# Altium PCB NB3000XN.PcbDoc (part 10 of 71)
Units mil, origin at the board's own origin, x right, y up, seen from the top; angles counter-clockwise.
Board outline 9527.56 x 6929.77 mil, 6 copper layers (Top Layer, GND+SHIELD, MidLayer1, MidLayer2, P2 - 3V3+5V0, Bottom Layer), stack 62.375 mil thick; 832 components, 1027 nets, 4655 pads, 4981 vias.
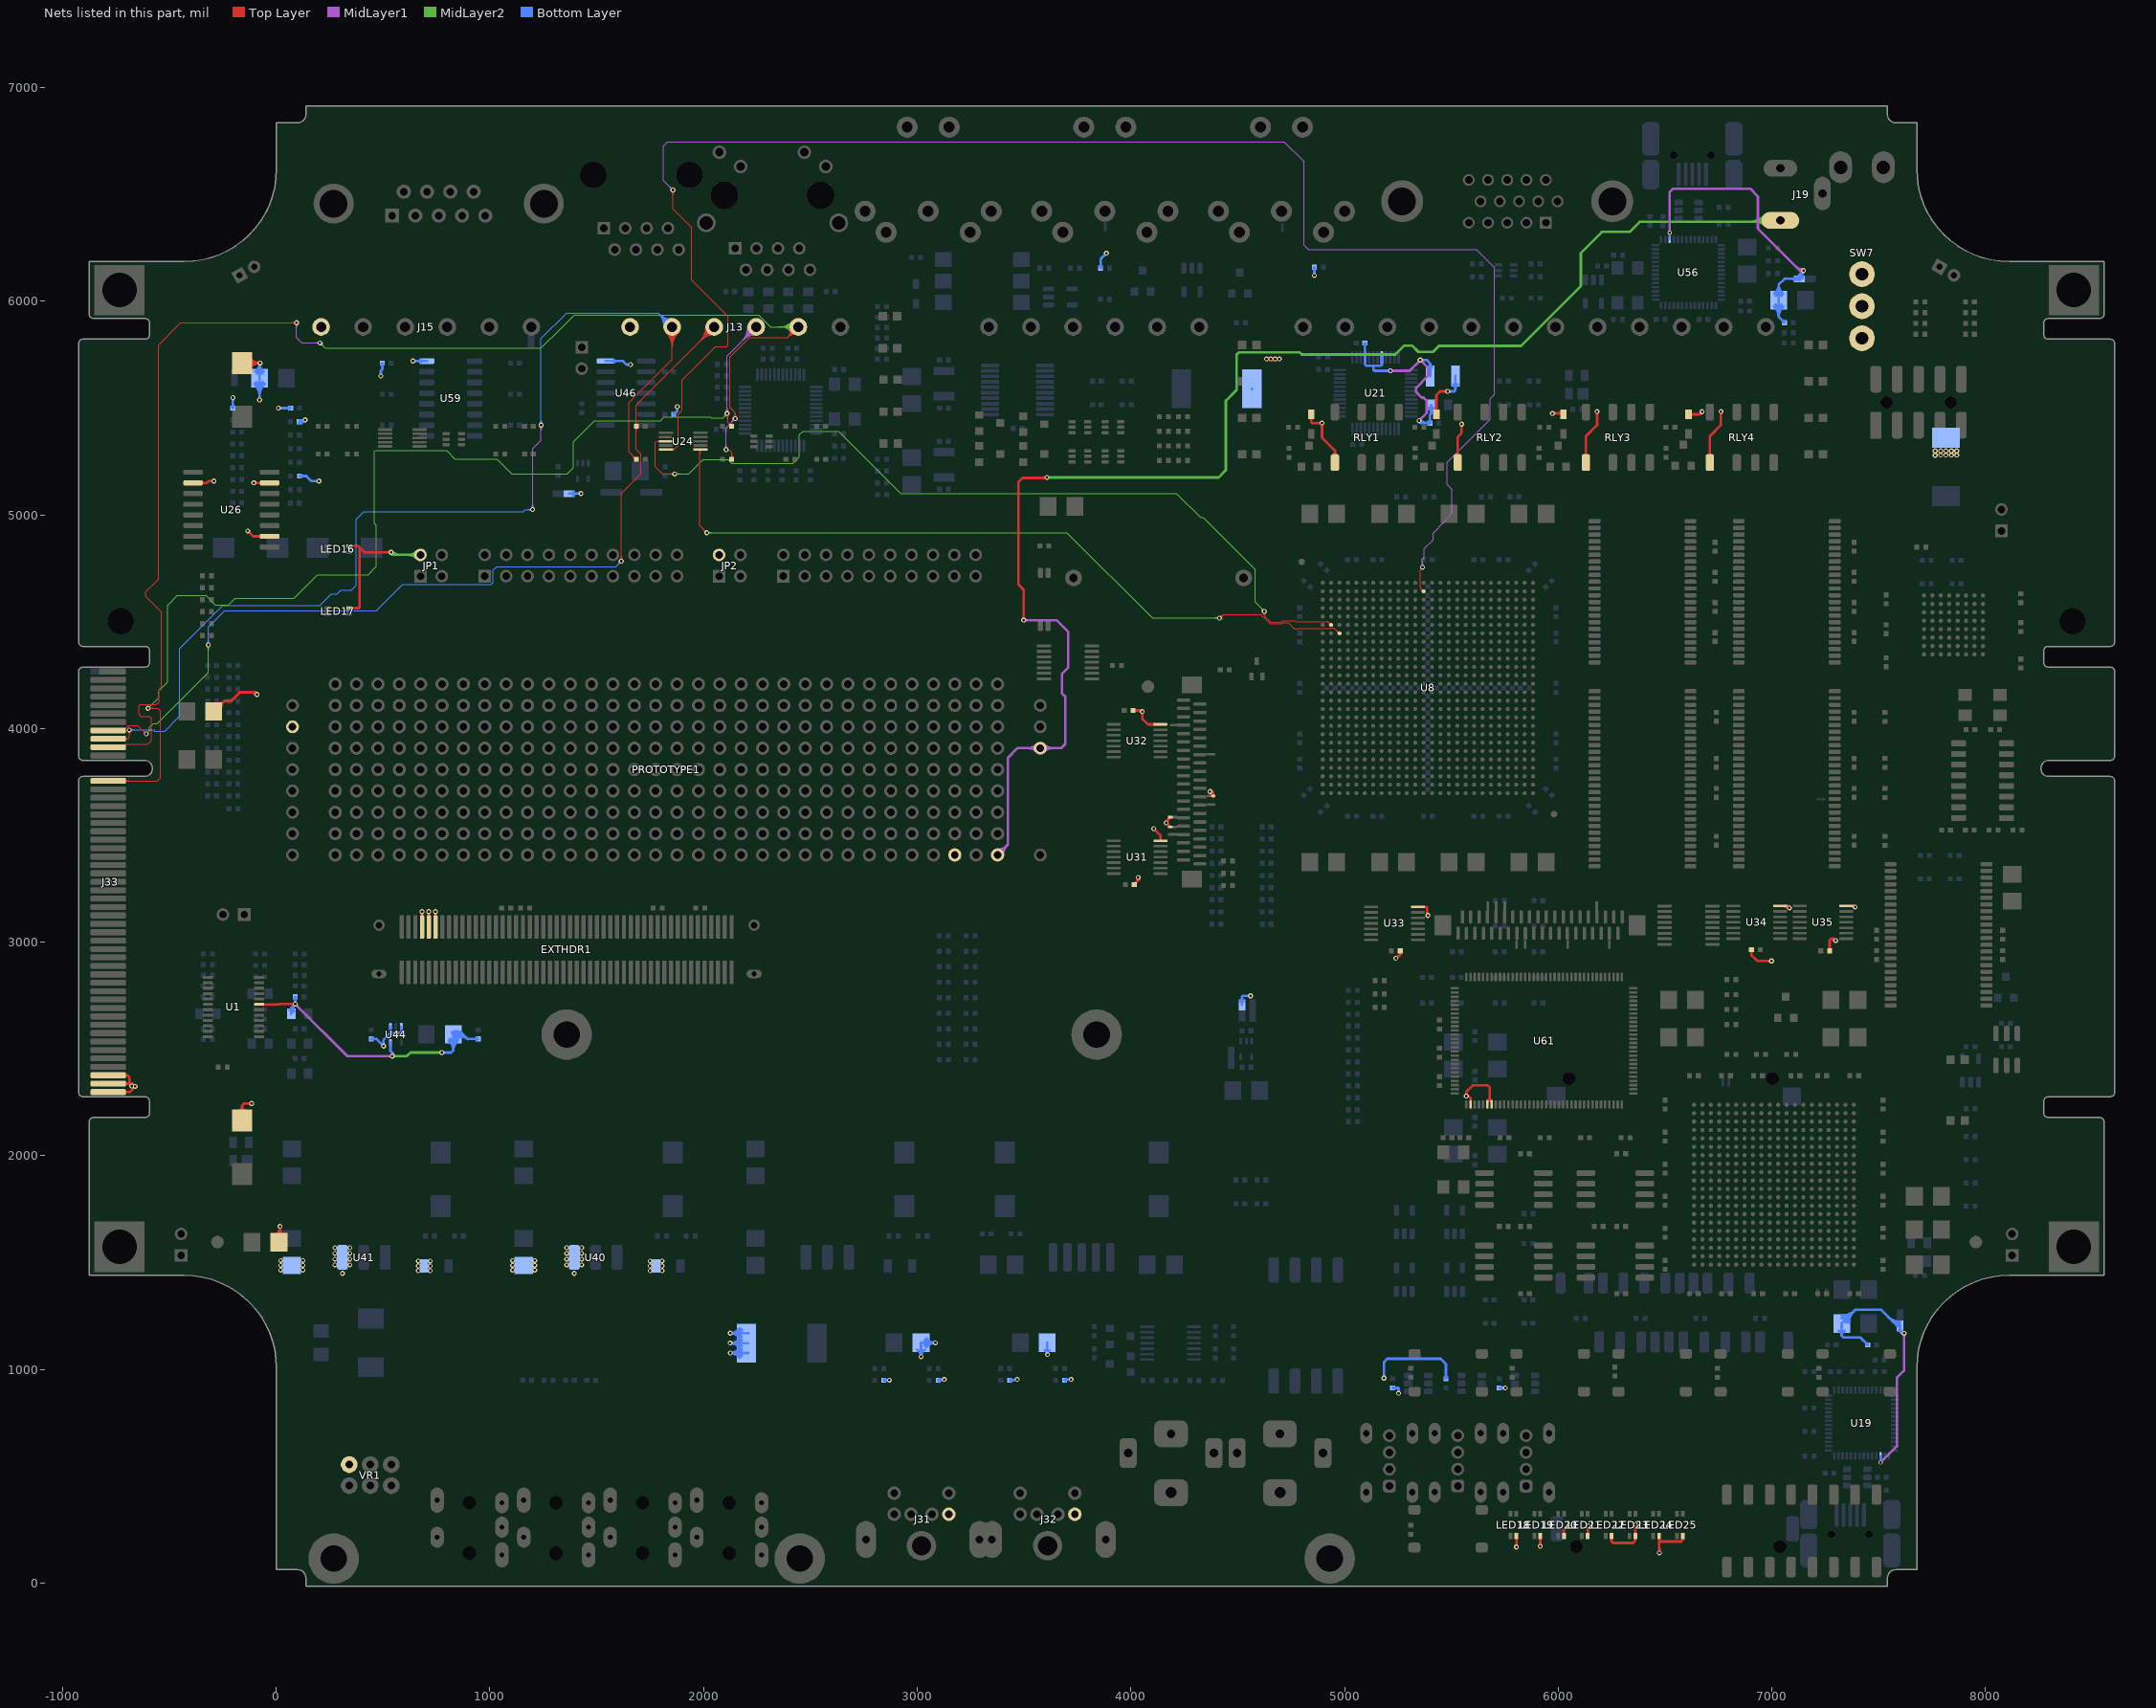
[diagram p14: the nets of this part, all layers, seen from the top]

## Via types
v1: diameter 23, hole 11.81, Top Layer to Bottom Layer, 3672 vias
v2: diameter 26, hole 11.81, Top Layer to Bottom Layer, 461 vias
v3: diameter 19, hole 11.81, Top Layer to Bottom Layer, tented both sides, 396 vias
v4: diameter 23.62, hole 11.81, Top Layer to Bottom Layer, 288 vias
v5: diameter 20, hole 11.81, Top Layer to Bottom Layer, 91 vias
v6: diameter 23, hole 11.81, Top Layer to Bottom Layer, tented both sides, 50 vias
v7: diameter 31, hole 11.81, Top Layer to Bottom Layer, 15 vias
v8: diameter 27.56, hole 11.81, Top Layer to Bottom Layer, tented both sides, 4 vias
v9: diameter 29, hole 11.81, Top Layer to Bottom Layer, 3 vias
v10: diameter 21, hole 11.81, Top Layer to Bottom Layer, 1 vias

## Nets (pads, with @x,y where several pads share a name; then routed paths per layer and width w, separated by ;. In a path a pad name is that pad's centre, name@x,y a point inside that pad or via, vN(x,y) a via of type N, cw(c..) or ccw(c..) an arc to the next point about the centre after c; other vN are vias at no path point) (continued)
5V0: C1.1 C2.1 C3.1 C4.1 C61.1 C62.1 C111.1 C112.2 C113.2 C114.2 C121.2 C122.2 C123.2 C124.2 C125.2 C130.1 C131.1 C134.1 C135.1 C145.2 C149.1 C152.2 D3.2 D4.2 D5.2 D6.2 EXTHDR1.89 EXTHDR1.91 EXTHDR1.93 F1.1 F2.2 J13.1 J15.1 J31.4 J32.4 J33.A47 J33.A48 J33.A49 JP1.2 JP2.2 L3.1 LED16.2 LED17.2 LED18.2 LED19.2 LED20.2 LED21.2 LED22.2 LED23.2 LED24.2 LED25.2 NT18.2 NT26.2 NT27.2 NT33.2 NT43.2 PROTOTYPE1.30 R82.1 R83.1 R86.1 R87.1 R141.2 R197.1 R199.1 R274.2 R275.2 R276.2 RLY1.1 RLY2.1 RLY3.1 RLY4.1 SW7.1 SW7.2 TP2.1 U26.2 U26.10 U26.15 U31.14 U32.14 U33.14 U34.14 U35.14 U40.3 U41.3 U44.1 U44.3 U46.14 U59.16 U61.2 U61.6 U61.7 VR1.3 | length 12012.6
  Top Layer w12: J33.A49@-785.98,2298.53 -686.47,2298.53 v1(-660,2325) -672.9,2337.9 J33.A48@-785.98,2337.9 ; J33.A47@-785.98,2377.27 -696.87,2377.27 -686.37,2366.77 -686.37,2339.27 ; J33.A49@-711.58,2293.03 cw(c-698.3,2279.75) -698.3,2298.53 cw(c-698.3,2317.31) J33.A49@-711.58,2304.03 ; J33.A48@-711.58,2332.4 cw(c-698.3,2319.12) -698.3,2337.9 cw(c-698.3,2356.68) J33.A48@-711.58,2343.4 ; J33.A47@-711.58,2371.77 cw(c-698.3,2358.49) -698.3,2377.27 cw(c-698.3,2396.05) J33.A47@-711.58,2382.77 ; v1@-665.5,2325 cw(c-678.78,2325) -669.39,2315.61 cw(c-660,2306.22) v1@-660,2319.5 ; U26.2@-389.13,5150 -325,5150 -316.62,5158.37 v1(-291.48,5158.37) ; U26.2@-351.56,5145.89 cw(c-341.64,5135.97) -341.64,5150 cw(c-341.64,5164.03) U26.2@-351.56,5154.11 ; v1@-295.36,5154.49 ccw(c-304.75,5145.1) -304.75,5158.37 ccw(c-304.75,5171.65) v1@-295.36,5162.26 ; C3.1@-292.01,4080 -242.38,4129.63 ; C3.1@-287.78,4104.88 ccw(c-281.31,4136.91) C3.1@-258.2,4113.81 ; C3.1@-285.4,4116.65 ccw(c-275.99,4163.23) -242.38,4129.63 ; C3.1@-270.69,4085.36 cw(c-237.71,4087.56) C3.1@-261.08,4110.93 ; C3.1@-258.71,4086.16 cw(c-202.66,4089.9) -242.38,4129.63 ; C2.1@-177.43,2207.25 ccw(c-190.75,2235.27) -159.72,2235.27 ; C1.1@-161.48,5711.04 C1.1@-159.72,5711.06 v1(-75.48,5711.04) ; C1.1@-161.48,5711.06 C1.1@-159.72,5711.06 ; C2.1@-159.72,2166.06 -159.72,2235.28 ; C2.1@-142.02,2207.25 cw(c-128.7,2235.27) -159.72,2235.27 ; C1.1@-136.63,5693.12 cw(c-100,5664.65) -100,5711.04 ; C1.1@-136.62,5728.99 ccw(c-99.98,5757.42) -99.98,5711.04 ; v1@-133.14,4919.54 cw(c-133.14,4903.85) -122.05,4914.94 ; v1(-133.14,4925.04) -132.14,4925.04 -107.1,4900 U26.10@-30.87,4900 ; -128.32,4170 cw(c-128.32,4121.31) v1@-93.89,4155.74 ; v1@-127.64,4925.04 ccw(c-116.78,4925.04) -124.46,4917.36 ; C1.1@-127.16,5685.75 cw(c-75.48,5645.59) v1(-75.48,5711.04) ; C1.1@-127.14,5736.34 ccw(c-75.48,5776.42) v1(-75.48,5711.04) ; v4@-119.11,2240.89 ccw(c-129.03,2230.97) -129.03,2245 ccw(c-129.03,2259.03) v4@-119.11,2249.11 ; v4(-115,2245) -150,2245 -159.72,2235.28 ; v1@-101.11,5146.11 cw(c-91.72,5136.72) -91.72,5150 cw(c-91.72,5163.28) v1@-101.11,5153.89 ; v1@-100,5150 U26.15@-30.87,5150 ; -99.35,4170 cw(c-99.35,4150.28) v1@-85.4,4164.22 ; v1(-90,4159.63) -100.37,4170 -169.63,4170 -210,4129.63 -242.38,4129.63 ; v1@-79.36,5707.15 ccw(c-88.75,5697.76) -88.75,5711.04 ccw(c-88.75,5724.32) v1@-79.36,5714.93 ; U26.10@-68.44,4895.89 ccw(c-78.36,4885.97) -78.36,4900 ccw(c-78.36,4914.03) U26.10@-68.44,4904.11 ; U26.15@-68.44,5145.89 ccw(c-78.36,5135.97) -78.36,5150 ccw(c-78.36,5164.03) U26.15@-68.44,5154.11 ; C4.1@-5.31,1626.84 ccw(c-33.61,1670) v1(18,1670) ; C4.1@1.27,1616.81 ccw(c-19.04,1647.78) 18,1647.78 ; C4.1@12.99,1595 18,1600.01 v1(18,1670) ; v1@14.11,1666.11 cw(c4.72,1656.72) 18,1656.72 cw(c31.28,1656.72) v1@21.89,1666.11 ; 18,1638.44 ccw(c52.49,1638.44) C4.1@28.1,1614.05 ; v1@18,1667.41 ccw(c81.46,1667.41) C4.1@36.59,1622.53 ; LED17.2@339.13,4563.78 387.52,4563.78 390.19,4566.44 390.19,4848.71 385.12,4853.78 ; LED16.2@339.13,4853.78 385.12,4853.78 ; v1@534.3,4821.15 ccw(c524.91,4811.76) 524.91,4825.04 ccw(c524.91,4838.32) v1@534.3,4828.93 ; v1(538.19,4825.04) 413.86,4825.04 385.12,4853.78 ; v1@678.46,3139.15 cw(c668.69,3129.38) 682.5,3129.38 ; EXTHDR1.93@682.5,3071.85 v1@682.5,3142.88 ; 682.5,3130.14 cw(c695.24,3130.14) v1@686.23,3139.15 ; v1@709.95,3139.15 cw(c700.18,3129.38) 714,3129.38 ; EXTHDR1.91@714,3071.85 v1@714,3142.88 ; 714,3130.14 cw(c726.74,3130.14) v1@717.73,3139.15 ; v1@741.45,3139.15 cw(c731.68,3129.38) 745.49,3129.38 ; EXTHDR1.89@745.49,3071.85 v1@745.49,3142.88 ; 745.49,3130.14 cw(c758.24,3130.14) v1@749.23,3139.15 ; v1@1656.22,5705.43 1657.65,5704 v1(1658,5704) ; C121.2@4010.67,4085 v1@4053.52,4085 ; C121.2@4014.78,4080.89 cw(c4024.7,4070.97) 4024.7,4085 ; C121.2@4014.78,4089.11 ccw(c4024.7,4099.03) 4024.7,4085 ; C124.2@4015.67,3270 4036.86,3291.19 4036.86,3300.71 v1(4034.19,3303.37) ; C124.2@4015.67,3275.81 ccw(c4015.67,3289.84) 4025.59,3279.92 ccw(c4035.51,3270) C124.2@4021.48,3270 ; C124.2@4023.1,3277.43 ccw(c4006.17,3294.35) v1@4028.96,3301.69 ; 4027.47,4085 cw(c4027.47,4053.65) 4049.64,4075.82 cw(c4040.25,4066.43) 4053.52,4066.43 cw(c4066.8,4066.43) v1@4057.41,4075.82 ; 4036.98,3291.31 ccw(c4027.18,3301.12) v1@4040.38,3305.37 ; v1(4053.52,4079.71) 4053.52,4046.48 4080,4020 U32.14@4138.5,4020 ; v1@4106.86,3525.87 cw(c4106.86,3511.84) 4116.78,3521.76 ; v1(4106.86,3531.37) 4115.19,3523.04 4115.5,3523.04 4138.5,3500.04 U31.14@4138.5,3475 ; v1@4112.36,3531.37 ccw(c4124.88,3531.37) 4116.02,3522.52 ; v1@4165.19,3552.87 cw(c4165.19,3536.13) 4177.03,3547.97 ; v1@4170.69,3558.37 cw(c4200.42,3558.37) NT26.2@4179.4,3579.4 ; 4177.32,3547.68 cw(c4169.64,3540) NT27.2@4180.5,3540 ; 4177.32,3577.32 ccw(c4169.64,3585) NT26.2@4180.5,3585 ; NT27.2@4185,3540 4166.63,3558.37 v1(4165.19,3558.37) 4165.19,3565.19 NT26.2@4185,3585 ; v1@4369.02,3699.59 cw(c4365.38,3679.54) NT33.2@4385.76,3679.54 ; v1@4371.16,3711.4 cw(c4367.99,3693.91) 4385.76,3693.91 ; v1@4376.86,3708.37 4385.76,3699.47 NT33.2@4385.76,3685 ; v1@4557.52,2741.71 4557.52,2747.71 4558.82,2749 v1(4560,2749) ; D3.2@4845,5471.26 4845,5435 4850,5430 v1(4895,5430) 4895,5361.59 4955,5301.59 RLY1.1@4955,5245 ; v1@4891.11,5433.89 cw(c4881.72,5443.28) 4881.72,5430 cw(c4881.72,5416.72) v1@4891.11,5426.11 ; v4(5240,2925) 5244.29,2925 5260.67,2941.37 C122.2@5260.67,2960 ; v4@5240,2930.81 ccw(c5240,2955.21) 5257.25,2937.96 ; C122.2@5256.56,2955.89 cw(c5246.64,2945.97) 5260.67,2945.97 cw(c5274.7,2945.97) C122.2@5264.78,2955.89 ; U33.14@5343.5,3165 5383.52,3165 5386.52,3162 5386.52,3128.71 v1(5390.19,3125.04) ; 5386.52,3147.17 ccw(c5412.32,3147.17) v1@5394.08,3128.93 ; D4.2@5423.64,5485.12 ccw(c5408.27,5500.49) 5430,5500.49 ccw(c5451.73,5500.49) D4.2@5436.36,5485.12 ; D4.2@5430,5471.26 5430,5561.48 5446.9,5578.37 v1(5482.52,5578.37) ; RLY2.1@5530,5245 5530,5365 5547.86,5382.86 v1(5547.86,5425.04) ; v4@5565.89,2284.11 ccw(c5555.97,2294.03) 5570,2294.03 ccw(c5584.03,2294.03) v4@5574.11,2284.11 ; U61.2@5590.19,2228.37 5589.69,2228.37 U61.2@5589.68,2240 5589.68,2270.31 5580,2280 v4(5570,2280) 5570,2300 5600,2330 5670,2330 5680,2320 5680,2259.71 ; U61.6@5668.19,2240 5668.19,2259.71 5680,2259.71 ; U61.6@5668.42,2253.19 cw(c5680,2246.17) 5680,2259.71 ; 5672.38,2259.71 cw(c5672.38,2237.46) U61.7@5688.11,2253.19 ; 5680,2272.77 ccw(c5707.69,2272.77) U61.7@5688.11,2253.19 ; U61.7@5688.11,2240 5688.11,2259.71 5680,2259.71 ; v1@5800.85,173.05 ccw(c5791.46,182.44) 5804.73,182.44 ccw(c5818.01,182.44) v1@5808.62,173.05 ; LED18.2@5804.73,223.69 v1(5804.73,169.16) ; v1@5912.3,176.26 ccw(c5903.42,185.15) 5915.98,185.15 ; 5915.98,186.16 ccw(c5929.97,186.16) v1@5920.08,176.26 ; LED19.2@5915.98,223.69 5915.98,172.58 v1(5916.19,172.37) ; v1(5972.86,5475.04) v1@5973.19,5475.04 ; v1@5976.86,5471.26 5976.86,5471.37 v1@5973.19,5475.04 ; 5994.29,5475.04 ccw(c5994.29,5509.47) D5.2@6018.64,5485.12 ; D5.2@6025,5475.04 v1@5973.19,5475.04 ; LED20.2@6027.23,223.69 6027.23,252.71 v1(6049.52,275) ; RLY3.1@6130,5245 6130,5369 6182,5421 v1(6182,5484) ; v1@6136.3,263.82 cw(c6126.91,254.43) 6140.19,254.43 cw(c6153.47,254.43) v1@6144.08,263.82 ; LED21.2@6138.48,223.69 6138.48,247.33 6140.19,249.04 v1(6140.19,267.71) ; 6249.72,195 LED22.2@6249.72,223.69 ; 6250,195 6256.63,188.37 6349.3,188.37 6360.97,200.04 6360.97,223.69 6360.97,274.82 v1(6361.19,275.04) ; v1@6357.3,271.15 cw(c6348.44,262.29) 6360.97,262.29 ; 6360.97,261.23 cw(c6375,261.23) v1@6365.08,271.15 ; v1@6469.64,145.6 ccw(c6460.25,154.99) 6473.52,154.99 ccw(c6486.8,154.99) v1@6477.41,145.6 ; LED24.2@6472.22,223.69 6472.22,195 ; v1(6473.52,141.71) 6473.52,165.37 6472.22,166.68 6472.22,195 ; LED25.2@6583.58,220.81 6583.58,203.58 6575,195 6472.22,195 ; D6.2@6610,5471.26 6661.41,5471.26 v1(6673.52,5483.37) ; 6657.97,5471.26 ccw(c6657.97,5496.93) v1@6676.12,5478.78 ; RLY4.1@6710,5245 6710,5369 6762,5421 v1(6762,5484) ; C123.2@6900.22,2960.89 cw(c6890.3,2950.97) 6904.33,2950.97 cw(c6918.36,2950.97) C123.2@6908.44,2960.89 ; C123.2@6904.33,2965 6904.33,2939.71 6931.66,2912.37 v1(6998.52,2912.37) ; v1@6994.64,2908.49 ccw(c6985.25,2899.1) 6985.25,2912.37 ccw(c6985.25,2925.65) v1@6994.64,2916.26 ; U34.14@7038.5,3170 7073.11,3170 7082.36,3160.75 v1@7082.7,3160.41 ; U34.14@7045.59,3170 cw(c7045.59,3123.98) v1@7078.13,3156.52 ; 7074.56,3170 cw(c7074.56,3152.95) v1@7086.62,3165.01 ; v1@7077.18,3165.94 ccw(c7067.02,3155.77) 7064.98,3170 cw(c7064.98,3150.37) v1@7078.86,3164.25 ; C125.2@7266.56,2964.11 ccw(c7256.64,2974.03) 7270.67,2974.03 ccw(c7284.7,2974.03) C125.2@7274.78,2964.11 ; C125.2@7270.67,2960 7270.67,3008.85 7278.52,3016.71 ; v1@7293.38,3006.43 ccw(c7278.52,3000.83) 7278.52,3016.71 ; v1(7298.52,3008.37) 7290.19,3016.71 7278.52,3016.71 ; U35.14@7348.5,3170 v1@7390,3170 ; U35.14@7364.65,3170 cw(c7364.65,3139.65) v1@7386.11,3161.11 ; v1@4891.11,5426.11 cw(c4881.72,5416.72) 4895,5416.72 ; v1@4891.11,5426.11 cw(c4881.72,5416.72) 4895,5416.72 ; 4895,5416.72 cw(c4908.28,5416.72) 4898.89,5426.11 ccw(c4908.28,5416.72) 4895,5416.72 ; 5680,2259.71 cw(c5680,2251.4) U61.7@5688.11,2253.19 ; 5680,2259.71 cw(c5680,2251.4) U61.7@5688.11,2253.19 ; v1(5804.73,169.16) 5807.19,166.71 v1(5804.73,169.16) ; 5986.14,5475.04 cw(c5986.14,5488.32) 5976.75,5478.93 ccw(c5986.14,5488.32) 5986.14,5475.04 ; 5986.14,5475.04 ccw(c5986.14,5461.76) 5976.75,5471.15 cw(c5986.14,5461.76) 5986.14,5475.04 ; v1@7082.7,3160.41 7085.3,3160.41 7085.91,3159.8 7085.91,3157.2 v1@7082.7,3160.41
  Top Layer w20: v1(4635,5730) v1@4680.19,5730
  MidLayer2 w12: v1@533.59,4820.44 ccw(c551.38,4838.23) 551.38,4813.08 ; v1(538.19,4825.04) 550.16,4813.08 JP1.2@675.1,4813.08 ; v1@542.08,4828.93 ccw(c580.35,4867.2) 580.35,4813.08 ; JP1.2@658.46,4796.44 ccw(c618.3,4756.28) 618.3,4813.08 ccw(c618.3,4869.88) JP1.2@658.46,4829.71 ; v1@1426.19,5100.04 v1(1426.52,5100.37) ; v4@5240,2920 v4(5240,2925)
  Bottom Layer w12: C113.2@-206.81,5504.19 ccw(c-216.73,5514.11) -202.7,5514.11 ccw(c-188.67,5514.11) C113.2@-198.59,5504.19 ; v1@-206.36,5545.15 cw(c-215.22,5536.3) -202.7,5536.3 ; C113.2@-202.7,5500.08 -202.7,5548.82 v1(-202.48,5549.04) ; -202.7,5535.22 cw(c-188.66,5535.22) v1@-198.59,5545.15 ; C111.1@-101.59,5612.47 cw(c-158.55,5555.5) -77.99,5555.5 cw(c2.57,5555.5) C111.1@-54.4,5612.47 ; C111.1@-97.3,5671.15 ccw(c-123.81,5708.52) v1@-77.99,5708.52 ; C111.1@-93.1,5620.95 cw(c-129.58,5584.47) -77.99,5584.47 cw(c-26.4,5584.47) C111.1@-62.88,5620.95 ; C111.1@-90.36,5661.37 ccw(c-107.33,5685.3) -77.99,5685.3 ccw(c-48.65,5685.3) C111.1@-65.63,5661.37 ; v1@-81.88,5542.08 ccw(c-91.27,5551.46) -77.99,5551.46 ccw(c-64.71,5551.46) v1@-74.1,5542.08 ; v1@-77.99,5537.99 v1(-77.99,5538.19) C111.1@-77.99,5640 v1@-77.99,5708.52 ; -77.99,5691.69 cw(c-56.12,5691.69) v1@-71.59,5707.15 ; v1(-75.48,5711.04) v1@-77.99,5708.52 ; C111.1@-58.68,5671.15 cw(c-32.18,5708.52) v1@-77.99,5708.52 ; v1@10.08,5500.08 C112.2@67.3,5500.08 ; v1@13.97,5496.39 cw(c22.89,5487.47) 22.89,5500.08 ; v1@13.97,5504.16 ccw(c23.83,5514.02) 23.83,5500.08 ; C112.2@63.19,5495.97 ccw(c53.27,5486.05) 53.27,5500.08 ccw(c53.27,5514.11) C112.2@63.19,5504.19 ; C114.2@105.24,5431.04 ccw(c112.71,5445.19) 124.02,5433.87 ; R141.2@109.15,5182.22 141.15,5182.22 165,5158.37 v1(200.19,5158.37) ; C114.2@110.84,5441.65 ccw(c120.66,5460.24) v1(135.52,5445.37) 123.52,5433.37 123.52,5433.51 120.52,5436.51 C114.2@108.13,5436.51 ccw(c108.13,5464.31) v1@131,5448.5 ; R141.2@112.91,5178.46 cw(c121.99,5169.38) 121.99,5182.22 cw(c121.99,5195.07) R141.2@112.91,5185.99 ; v1@196.3,5154.49 ccw(c186.91,5145.1) 186.91,5158.37 ccw(c186.91,5171.65) v1@196.3,5162.26 ; C145.2@445,2547.71 468.86,2547.7 470.52,2546.04 470.52,2545.71 v1(502.52,2513.71) 502.52,2543.16 534.41,2575.04 534.41,2583.37 ; C145.2@449.11,2543.6 cw(c459.03,2533.68) 459.03,2547.7 cw(c459.03,2561.74) C145.2@449.11,2551.81 ; v4(490,5650) 490,5675 496.44,5681.44 C149.1@496.44,5710.08 ; C149.1@492.33,5705.97 cw(c482.41,5696.05) 496.44,5696.05 cw(c510.47,5696.05) C149.1@500.55,5705.97 ; v1@497.02,2513.71 ccw(c483.75,2513.71) 493.14,2523.1 ccw(c502.52,2532.49) v1@502.52,2519.21 ; v1@498.64,2517.6 ccw(c489.25,2526.99) 502.52,2526.99 ccw(c515.8,2526.99) v1@506.41,2517.6 ; U44.1@534.41,2605.78 534.41,2583.37 ; 585,2575 550.04,2575 542.74,2575.04 538.58,2579.21 534.41,2583.37 ; 585.59,2575.59 U44.3@585.59,2605.78 ; v4(639.92,5720.08) U59.16@704.59,5720.08 ; v4@644.03,5715.97 cw(c653.95,5706.05) 653.95,5720.08 cw(c653.95,5734.11) v4@644.03,5724.19 ; U59.16@677.44,5714.58 ccw(c664.16,5701.3) 664.16,5720.08 ccw(c664.16,5738.86) U59.16@677.44,5725.58 ; NT18.2@1371.1,5099.76 1425.91,5099.76 v1(1426.52,5100.37) ; NT18.2@1388.25,5092.87 cw(c1404.89,5076.23) 1404.89,5099.76 cw(c1404.89,5123.3) NT18.2@1388.25,5106.66 ; 1411.77,5099.76 ccw(c1411.77,5115.13) v1@1422.64,5104.26 ; 1414.72,5099.76 cw(c1414.72,5088.57) v1@1422.64,5096.49 ; U46.14@1542.57,5720.08 1622.82,5720.08 1638.9,5704 v1(1658,5704) ; U46.14@1578.17,5715.97 cw(c1588.09,5706.05) 1588.09,5720.08 cw(c1588.09,5734.11) U46.14@1578.17,5724.19 ; v1@1654.11,5700.11 ccw(c1644.72,5690.72) 1644.72,5704 ccw(c1644.72,5717.28) v1@1654.11,5707.89 ; C152.2@1860.67,5470 1877,5486.33 v1(1877,5507) ; C152.2@1860.67,5475.81 ccw(c1860.67,5489.84) 1870.59,5479.92 ccw(c1880.51,5470) C152.2@1866.48,5470 ; v1@1873.11,5503.11 cw(c1863.72,5493.72) 1877,5493.72 cw(c1890.28,5493.72) v1@1880.89,5503.11 ; v1@2128.14,1119.69 cw(c2137.53,1110.3) 2137.53,1123.58 cw(c2137.53,1136.86) v1@2128.14,1127.47 ; v1@2128.89,1073.27 cw(c2138.28,1063.88) 2138.28,1077.16 cw(c2138.28,1090.43) v1@2128.89,1081.04 ; v1@2128.89,1166.11 cw(c2138.28,1156.72) 2138.28,1170 cw(c2138.28,1183.28) v1@2128.89,1173.89 ; 2147.49,1077.15 ccw(c2147.49,1113.99) F2.2@2178.09,1093.49 ; 2147.49,1170 cw(c2147.49,1133.17) F2.2@2178.09,1153.67 ; 2148.84,1077.15 cw(c2148.84,1039.81) F2.2@2178.84,1062.05 ; 2148.84,1170 ccw(c2148.84,1207.35) F2.2@2178.84,1185.1 ; F2.2@2168.12,1100.16 cw(c2125,1129.06) v1(2125,1077.15) ; F2.2@2168.12,1146.99 ccw(c2125,1118.1) v1(2125,1170) ; F2.2@2168.83,1100.69 ccw(c2124.26,1068.73) v1(2124.25,1123.58) ; F2.2@2168.83,1146.46 cw(c2124.26,1178.43) v1(2124.25,1123.58) ; F2.2@2169.2,1054.91 ccw(c2125,1022.13) v1(2125,1077.15) ; F2.2@2169.2,1192.25 cw(c2125,1225.02) v1(2125,1170) ; F2.2@2178.58,1107.68 ccw(c2147.63,1085.49) 2147.63,1123.58 ccw(c2147.63,1161.67) F2.2@2178.58,1139.47 ; F2.2@2209.25,1123.58 F2.2@2200.75,1123.58 v1(2124.25,1123.58) ; F2.2@2210,1077.15 2200.75,1077.15 v1(2125,1077.15) ; F2.2@2210,1170 2200.75,1170 v1(2125,1170) ; R82.1@2843.23,950 v1(2870,950) v1@2872.23,950 ; R82.1@2846.99,946.24 cw(c2856.07,937.16) 2856.07,950 cw(c2856.07,962.84) R82.1@2846.99,953.76 ; v1@2866.11,946.11 ccw(c2856.72,936.72) 2856.72,950 ccw(c2856.72,963.28) v1@2866.11,953.89 ; C62.1@2999.97,1092.98 cw(c2978.81,1060) v1(3017.99,1060) ; v1@3014.1,1063.89 ccw(c3004.71,1073.28) 3017.99,1073.28 ccw(c3031.27,1073.28) v1@3021.88,1063.89 ; C62.1@3035.05,1112.12 cw(c3060.9,1092.61) 3060.9,1125 cw(c3060.9,1157.39) C62.1@3035.05,1137.88 ; C62.1@3036.01,1092.98 ccw(c3057.17,1060) v1(3017.99,1060) ; C62.1@3044.62,1104.89 cw(c3085,1074.41) v1(3085,1125) cw(c3085,1175.59) C62.1@3044.62,1145.11 ; v1@3081.11,1121.11 ccw(c3071.72,1111.72) 3071.72,1125 ccw(c3071.72,1138.28) v1@3081.11,1128.89 ; v1@3087.19,1124.71 3087.19,1125 v1(3085,1125) C62.1@3017.99,1125 v1(3017.99,1060) ; R83.1@3099.13,950 3123.52,950 v1(3126.86,953.37) ; R83.1@3102.89,946.24 cw(c3111.97,937.16) 3111.97,950 cw(c3111.98,962.84) R83.1@3102.89,953.76 ; R83.1@3105.43,950 ccw(c3105.43,974.8) v1@3122.97,957.26 ; R86.1@3433.23,950 3458.23,950 3461.61,953.37 v1(3468.19,953.37) ; R86.1@3436.99,946.24 cw(c3446.07,937.16) 3446.07,950 cw(c3446.07,962.84) R86.1@3436.99,953.76 ; 3446.76,950 ccw(c3446.76,974.8) v1@3464.3,957.26 ; C61.1@3597.62,1089.35 cw(c3592.94,1075.04) v1@3607.99,1075.04 ; C61.1@3607.99,1088.13 ccw(c3628.13,1088.13) v1@3613.89,1073.89 ; C61.1@3607.99,1125 v1@3607.99,1075.04 ; C61.1@3618.36,1089.35 ccw(c3623.04,1075.04) v1@3607.99,1075.04 ; R87.1@3689.13,950 3692.51,953.37 v1(3720.86,953.37) ; R87.1@3692.89,946.73 cw(c3708.93,930.69) 3708.93,953.37 ; v1@3716.97,949.49 ccw(c3707.58,940.1) 3707.58,953.37 ccw(c3707.58,966.65) v1@3716.97,957.26 ; R197.1@3855.06,6159.25 ccw(c3845.98,6168.33) 3858.82,6168.33 ccw(c3871.66,6168.33) R197.1@3862.58,6159.25 ; R197.1@3858.82,6155 3858.82,6197.67 v1(3886.19,6225.04) ; v1@3880.69,6225.04 cw(c3867.41,6225.04) 3876.8,6215.65 cw(c3886.19,6206.26) v1@3886.19,6219.54 ; NT43.2@4513.34,2723.25 ccw(c4496.7,2739.89) 4520.24,2739.89 ccw(c4543.77,2739.89) NT43.2@4527.13,2723.25 ; NT43.2@4520.24,2706.1 4520.24,2745 4524.24,2749 v1(4560,2749) ; v1@4556.11,2745.11 ccw(c4546.72,2735.72) 4546.72,2749 ccw(c4546.72,2762.28) v1@4556.11,2752.89 ; R199.1@4855.06,6155.75 cw(c4845.98,6146.67) 4858.82,6146.67 cw(c4871.66,6146.67) R199.1@4862.58,6155.75 ; v1(4858.82,6121.08) R199.1@4858.82,6160 ; v4@5180.89,964.11 ccw(c5170.97,974.03) 5185,974.03 ccw(c5199.03,974.03) v4@5189.11,964.11 ; v4(5185,960) 5185,1035 5200,1050 5450,1050 5475,1025 R275.2@5475,956.18 ; R274.2@5225,913.82 5252.75,913.82 5252.86,913.71 v1(5252.86,888.71) ; R274.2@5229.25,910.06 cw(c5238.33,900.98) 5238.33,913.82 cw(c5238.33,926.66) R274.2@5229.25,917.58 ; v1@5248.97,892.6 ccw(c5239.58,901.99) 5252.86,901.99 ccw(c5266.14,901.99) v1@5256.75,892.6 ; R275.2@5471.24,959.94 ccw(c5462.16,969.02) 5475,969.02 ccw(c5487.84,969.02) R275.2@5478.76,959.94 ; v1(5482.52,5578.37) 5513.37,5578.37 5519.06,5584.06 L3.1@5519.06,5650 ; L3.1@5509.38,5610.8 cw(c5486.02,5587.43) 5519.06,5587.43 cw(c5552.09,5587.43) L3.1@5528.73,5610.8 ; R276.2@5725,913.82 v1(5752.75,913.82) ; R276.2@5729.25,910.06 cw(c5738.33,900.98) 5738.33,913.82 cw(c5738.33,926.66) R276.2@5729.25,917.58 ; v1@5748.86,909.93 ccw(c5739.47,900.54) 5739.47,913.82 ccw(c5739.47,927.1) v1@5748.86,917.71 ; v1(7082.02,3160.41) 7082.84,3160.41 7084.41,3158.84 v1@7084.41,3158.7
  other v1: 3610,1070 310,1450 1395,1450 665,1462.5 720.83,1462.5 1750,1462.5 1805.83,1462.5 21.14,1465 125,1465 1106.14,1465 1210,1465 665,1485 720.83,1485 1750,1485 1805.83,1485 21.14,1487.5 125,1487.5 1106.14,1487.5 1210,1487.5 275,1490 345,1490 1360,1490 1430,1490 665,1507.5 720.83,1507.5 1750,1507.5 1805.83,1507.5 21.14,1510 125,1510 1106.14,1510 1210,1510 275,1516.67 345,1516.67 1360,1516.67 1430,1516.67 275,1543.33 345,1543.33 1360,1543.33 1430,1543.33 275,1570 345,1570 1360,1570 1430,1570 -675.7,2327 682.35,3143.04 713.84,3143.04 745.34,3143.04 7390,3165 4370,3705 -105,5150 10.08,5500.28 4655,5730 4675,5730 4695,5730
+5V_VIDOUT: C97.1 C98.1 C99.2 L3.2 U21.40 U21.44 | length 1467.3
  MidLayer1 w12: v4(5215,5675) 5305.15,5675 v1(5355.19,5725.04) 5390.19,5690.04 5390.19,5650 5335,5594.81 5335,5575.83 5361.33,5549.5 5369.91,5549.5 5385,5534.41 5385,5478.11 5348.6,5441.71 v1(5348.52,5441.71) ; v4@5219.11,5670.89 cw(c5229.03,5660.97) 5229.03,5675 cw(c5229.03,5689.03) v4@5219.11,5679.11 ; v1@5348.52,5447.21 ccw(c5348.52,5460.66) 5358.04,5451.15 ; v1@5349.69,5725.04 cw(c5336.41,5725.04) 5345.8,5715.65 cw(c5355.19,5706.26) 5355.19,5719.54 cw(c5355.19,5706.26) 5364.58,5715.65 cw(c5373.97,5725.04) v1@5360.69,5725.04 ; v1@5354.02,5441.71 cw(c5367.13,5441.71) 5357.86,5450.97
  Bottom Layer w12: C97.1@5091.56,5800.89 cw(c5081.64,5790.97) 5095.67,5790.97 cw(c5109.7,5790.97) C97.1@5099.78,5800.89 ; C97.1@5095.67,5805 5095.67,5737.32 5095.67,5704.33 5102.2,5697.8 5135,5697.8 ; U21.40@5095.79,5713.8 ccw(c5104.11,5709.28) 5097.41,5702.59 ; 5174.16,5703.01 ccw(c5168.57,5708.6) U21.44@5174.53,5713.8 ; U21.44@5174.53,5737.32 5174.53,5703.37 5168.95,5697.8 5135,5697.8 ; v4@5210.89,5670.89 ccw(c5200.97,5660.97) 5200.97,5675 ccw(c5200.97,5689.03) v4@5210.89,5679.11 ; v4(5215,5675) 5140,5675 5135,5680 5135,5697.8 ; v1@5343.93,5437.11 ccw(c5361.1,5454.28) 5361.1,5430 ; v1(5348.52,5441.71) 5360.23,5430 C98.1@5399.33,5430 5399.33,5466.71 5405.63,5473.01 C99.2@5405.63,5515 ; v1@5352.41,5445.6 ccw(c5390.07,5483.25) C98.1@5390.07,5430 ; v1(5355.19,5725.04) 5384.28,5725.04 5400.94,5708.37 ; v1@5359.08,5721.15 cw(c5368.47,5711.76) 5368.47,5725.04 cw(c5368.47,5738.32) v1@5359.08,5728.93 ; L3.2@5392.29,5690.13 ccw(c5377.39,5708.37) 5400.94,5708.37 ; C98.1@5395.22,5425.89 ccw(c5385.3,5415.97) 5385.3,5430 ccw(c5385.3,5444.03) 5395.22,5434.11 ccw(c5385.3,5444.03) 5399.33,5444.03 ccw(c5413.36,5444.03) C98.1@5403.44,5434.11 ; C99.2@5395.95,5500.4 cw(c5372.59,5477.04) 5405.63,5477.04 cw(c5438.67,5477.04) C99.2@5415.31,5500.4 ; L3.2@5400.94,5650 5400.94,5708.37 ; L3.2@5409.6,5690.13 cw(c5424.5,5708.37) 5400.94,5708.37
+B: D10.2 J19.1 PROTOTYPE1.32 SW7.3 TP3.1 | length 7281.1
  Top Layer w12: v1@3494.64,4511.26 ccw(c3485.25,4520.65) 3498.52,4520.65 ccw(c3511.8,4520.65) v1@3502.41,4511.26 ; v1(3498.52,4507.37) 3498.52,4650.04 3473.52,4675.04 3473.52,5153.52 3493,5173 3602.96,5173 3605,5175.04 v1(3606.86,5175.04) ; 3588.65,5173 ccw(c3588.65,5193.25) v1@3602.97,5178.93
  MidLayer1 w12: PROTOTYPE1.32@3376.12,3408.23 3424.62,3456.74 3424.62,3863.9 3468.96,3908.23 TP3.1@3576.12,3908.23 3673.23,3908.23 3693.35,3928.35 3693.35,4067.27 ; PROTOTYPE1.32@3376.12,3421.23 ccw(c3376.12,3452.62) 3398.31,3430.43 ccw(c3420.51,3408.23) PROTOTYPE1.32@3389.12,3408.23 ; PROTOTYPE1.32@3376.12,3433.23 ccw(c3376.12,3493.59) 3418.8,3450.91 ccw(c3461.48,3408.23) PROTOTYPE1.32@3401.12,3408.23 ; v1(3498.52,4507.37) 3652.63,4507.37 3707.17,4452.83 3707.17,4285.54 3677.02,4255.4 3677.02,4166.14 3693.35,4149.81 3693.35,4067.27 ; v1@3502.41,4503.49 cw(c3511.8,4494.1) 3511.8,4507.37 cw(c3511.8,4520.65) v1@3502.41,4511.26 ; TP3.1@3559.15,3891.26 ccw(c3518.18,3850.29) 3518.18,3908.23 ccw(c3518.18,3966.18) TP3.1@3559.15,3925.21 ; TP3.1@3593.09,3891.26 cw(c3634.06,3850.29) 3634.06,3908.23 cw(c3634.06,3966.18) TP3.1@3593.09,3925.21 ; 3693.35,4071.88 3693.35,4067.27
  MidLayer2 w12: v1(3606.86,5175.04) 4410.04,5175.04 4445,5210 4445,5534.45 4495,5584.45 4495,5750 4506.5,5761.5 4788.91,5761.5 4799.86,5750.54 5238.25,5750.54 5280.71,5793 5316.15,5793 5345.97,5763.19 5414.6,5763.19 5442.22,5790.81 5825.66,5790.81 6106,6071.15 6106,6226 6205,6325 6335,6325 6381.99,6371.99 6711.65,6371.99 6712.08,6372.41 7033.78,6372.41 J19.1@7040,6378.63 ; v1@3610.75,5171.15 cw(c3620.14,5161.76) 3620.14,5175.04 cw(c3620.14,5188.32) v1@3610.75,5178.93 ; 6895.22,6372.41 ccw(c6895.22,6474.2) J19.1@6967.19,6402.23 ; 6924.19,6372.41 ccw(c6924.19,6445.23) J19.1@6975.68,6393.74 ; 6925.23,6372.41 cw(c6925.23,6313.07) J19.1@6967.19,6355.03
  other v4: 7765,5280 7790,5280.1 7815.1,5280.1 7840.2,5280.1 7865.3,5280.1 7765,5300 7790,5300.1 7815.1,5300.1 7840.2,5300.1 7865.3,5300.1
A3V3_CODEC: C19.1 C22.1 C146.1 C147.2 U1.19 U44.5 | length 2293.9
  Top Layer w12: U1.19@-78.48,2710.37 U1.19@-79.84,2709.02 13.64,2709.02 15,2710.37 v1(89.19,2710.37) ; v1@85.3,2706.49 ccw(c75.91,2697.1) 75.91,2710.37 ccw(c75.91,2723.65) v1@85.3,2714.26
  MidLayer1 w12: v1@89.19,2704.87 cw(c89.19,2691.6) 98.58,2700.99 cw(c107.97,2710.37) v1@94.69,2710.37 ; v1(89.19,2710.37) 332.86,2466.71 v1(543.19,2466.71) ; v1@539.3,2462.82 ccw(c529.91,2453.43) 529.91,2466.71 ccw(c529.91,2479.99) v1@539.3,2470.6
  MidLayer2 w12: v1(543.19,2466.71) 611.71,2466.71 628.37,2483.37 v1(775.19,2483.37) ; v1@547.08,2462.82 cw(c556.47,2453.43) 556.47,2466.71 cw(c556.47,2479.99) v1@547.08,2470.6 ; v1@771.3,2479.49 ccw(c761.91,2470.1) 761.91,2483.37 ccw(c761.91,2496.65) v1@771.3,2487.26
  Bottom Layer w4: v1(89.19,2710.37) 89.33,2710.51 v1(89.19,2710.37)
  Bottom Layer w12: C19.1@64.64,2682.22 ccw(c59.96,2691.81) 70.63,2691.81 ; C19.1@70.63,2665 70.63,2691.81 ; C19.1@72.16,2670.63 cw(c94.35,2680.93) 77.05,2698.23 ; C19.1@76.63,2682.22 cw(c81.3,2691.81) 70.63,2691.81 ; C19.1@83.04,2675.68 cw(c110.93,2688.63) v1(89.19,2710.37) ; v1@83.69,2710.37 cw(c70.41,2710.37) 79.8,2700.99 cw(c89.19,2691.6) v1@89.19,2704.87 ; C22.1@85.22,2740.89 cw(c75.64,2731.31) 89.19,2731.31 ; v1@85.3,2714.26 ccw(c75.91,2723.65) 89.19,2723.65 ccw(c102.47,2723.65) v1@93.08,2714.26 ; 89.19,2730.63 cw(c103.7,2730.63) C22.1@93.44,2740.89 ; C22.1@89.33,2745 89.19,2744.86 v1(89.19,2710.37) ; U44.5@534.41,2530.97 534.41,2491.49 543.19,2482.71 v1(543.19,2466.71) ; v1@539.3,2470.6 ccw(c529.91,2479.99) 543.19,2479.99 ccw(c556.47,2479.99) v1@547.08,2470.6 ; 544.1,2481.8 cw(c530.4,2468.11) v1@549.65,2466 ; v1(775.19,2483.37) 818.48,2483.37 828.48,2493.37 ; v1@779.08,2479.49 cw(c788.47,2470.1) 788.47,2483.37 cw(c788.47,2496.65) v1@779.08,2487.26 ; C146.1@807.17,2538.76 cw(c769.51,2493.38) 828.48,2493.38 ; C146.1@814.84,2547.99 cw(c790.72,2518.93) 828.48,2518.93 cw(c866.25,2518.93) C146.1@842.13,2547.99 ; C146.1@821.75,2577.43 cw(c841.68,2538.98) 872.3,2569.6 ; C146.1@826.66,2574.21 cw(c847.17,2552.86) 868.11,2573.79 ; C146.1@827.27,2566.77 cw(c849.59,2523.7) 883.9,2558 ; C146.1@832.8,2556.12 cw(c857.51,2508.43) 895.49,2546.41 ; C146.1@834.98,2565.55 cw(c855.66,2544.03) 876.76,2565.14 ; C146.1@843.29,2556.9 cw(c864.14,2535.2) 885.42,2556.48 ; C146.1@849.8,2538.76 ccw(c887.46,2493.38) 828.48,2493.38 ; C146.1@851.6,2548.25 cw(c872.62,2526.37) 894.07,2547.82 ; C146.1@860.41,2558.66 cw(c873.52,2554.67) 873.52,2568.37 ; C146.1@860.41,2578.09 ccw(c873.52,2582.08) 873.52,2568.37 ; C147.2@940.89,2543.6 ccw(c930.97,2533.68) 930.97,2547.71 ccw(c930.97,2561.73) C147.2@940.89,2551.81 ; C147.2@945,2547.71 894.19,2547.71 873.52,2568.37 ; 70.63,2691.81 v1(89.19,2710.37) ; 828.48,2493.38 C146.1@828.48,2568.37 873.52,2568.37
A3V3_USBA: C170.2 C171.1 NT45.2 U56.3 | length 2097.6
  MidLayer1 w12: v5(6521.42,6320.66) 6521.42,6510.42 6538,6527 6898,6527 6935,6490 6935,6455 6935,6450 6935,6339.59 7130.89,6143.71 v1(7148.19,6143.71) ; 7109.26,6165.33 ccw(c7148.19,6204.26) v1@7148.19,6149.21 ; 7129.75,6144.85 ccw(c7148.19,6163.29) v1@7148.19,6137.21 ; v1@7144.3,6139.82 ccw(c7134.91,6130.43) 7134.91,6143.71 ccw(c7134.91,6156.99) v1@7144.3,6147.6
  Bottom Layer w8: v5@6517.17,6316.42 cw(c6506.93,6306.18) 6521.42,6306.18 cw(c6535.9,6306.18) v5@6525.66,6316.42 ; U56.3@6521.42,6289.33 v5(6521.42,6320.66)
  Bottom Layer w12: C171.1@7009.98,5975.99 cw(c6967.23,5927.33) 7032.01,5927.33 ; C171.1@7011.57,6035.32 ccw(c6979.27,6077) 7032.01,6077 ; C171.1@7017.9,5985.01 cw(c6990.52,5953.84) 7032.01,5953.84 cw(c7073.49,5953.84) C171.1@7046.11,5985.01 ; C171.1@7018.92,6025.83 ccw(c6998.24,6052.53) 7032.01,6052.53 ccw(c7065.78,6052.53) C171.1@7045.1,6025.83 ; C171.1@7052.45,6035.32 cw(c7084.74,6077) 7032.01,6077 ; C170.2@7053.52,5900 ccw(c7039.49,5900) 7049.41,5909.92 ccw(c7059.33,5919.84) C170.2@7059.33,5905.81 ; C171.1@7054.03,5975.99 ccw(c7096.79,5927.33) 7032.01,5927.33 ; C170.2@7059.33,5900 7032.01,5927.32 ; NT45.2@7111.75,6098.34 ccw(c7095.11,6081.7) 7095.11,6105.24 ccw(c7095.11,6128.77) NT45.2@7111.75,6112.13 ; NT45.2@7123.15,6113.11 ccw(c7114.91,6124.41) 7128.9,6124.41 ; NT45.2@7128.17,6096.16 cw(c7144.73,6109.85) 7129.53,6125.05 ; NT45.2@7134.64,6113.11 cw(c7142.89,6124.41) 7128.9,6124.41 ; NT45.2@7137.41,6103.8 cw(c7154.95,6118.29) 7138.86,6134.38 ; v1@7142.69,6143.71 cw(c7129.41,6143.71) 7138.8,6134.32 cw(c7148.19,6124.93) v1@7148.19,6138.21 ; NT45.2@7146.66,6111.45 cw(c7165.16,6126.74) v1(7148.19,6143.71) 7128.9,6124.42 ; 7032.01,5927.32 C171.1@7032.01,6005 7032.01,6077.01 ; 7032.01,6077.01 7060.24,6105.24 NT45.2@7128.9,6105.24 7128.9,6124.42
A3V3_USBB: C88.2 C89.1 NT10.2 U19.3 | length 1731
  MidLayer1 w12: v5(7508.58,564.34) 7585,640.76 7585,960 7618.86,993.86 v1(7618.86,1169.71) ; v1@7614.97,1165.82 cw(c7605.58,1156.43) 7618.86,1156.43 cw(c7632.14,1156.43) v1@7622.75,1165.82
  Bottom Layer w8: v5@7504.34,568.58 ccw(c7494.1,578.82) 7508.58,578.82 ccw(c7523.07,578.82) v5@7512.83,568.58 ; v5(7508.58,564.34) U19.3@7508.58,595.67
  Bottom Layer w12: C89.1@7312.55,1180.99 cw(c7301.49,1157.99) 7327.01,1157.99 ; C89.1@7327.01,1240.31 ccw(c7327.01,1301.4) 7370.21,1258.2 ; C89.1@7327.01,1252.31 ccw(c7327.01,1342.37) 7390.7,1278.69 ; C89.1@7341.47,1180.99 ccw(c7352.52,1157.99) 7327.01,1157.99 ; C89.1@7348.38,1218.94 cw(c7390.47,1218.94) C89.1@7360.71,1248.7 ; C89.1@7360.38,1218.94 cw(c7431.44,1218.94) 7381.19,1269.18 ; C88.2@7443.52,1115 ccw(c7429.49,1115) 7439.41,1124.92 ccw(c7449.33,1134.84) C88.2@7449.33,1120.81 ; C88.2@7449.33,1115 7414.33,1150 7335,1150 7327.01,1157.99 ; 7542.3,1247.7 ccw(c7599.76,1305.16) NT10.2@7599.76,1223.9 ; 7562.79,1227.21 ccw(c7599.76,1264.19) NT10.2@7599.76,1211.9 ; 7583.27,1206.73 ccw(c7599.76,1223.22) NT10.2@7599.76,1199.9 ; NT10.2@7595.32,1184.97 cw(c7591.61,1177.71) 7599.76,1177.71 ; NT10.2@7604.2,1184.97 ccw(c7607.92,1177.71) 7599.76,1177.71 ; v1(7618.86,1169.71) 7607.76,1169.71 7599.76,1177.71 ; 7327.01,1157.99 C89.1@7327.01,1215 7392.01,1280 7510,1280 7586.1,1203.9 NT10.2@7599.76,1203.9 7599.76,1177.71
ADC#.ADC0: J13.2 J33.A9 R133.1 | length 6866.3
  Top Layer w4: J33.A9@-785.98,3952.07 -694.48,3952.07 ; J33.A9@-710.71,3947.62 cw(c-702.15,3941.64) -702.15,3952.07 cw(c-702.15,3962.51) J33.A9@-710.71,3956.53 ; J33.A9@-707.43,3945.32 cw(c-694.48,3936.27) -694.48,3952.07 ; J33.A9@-707.43,3958.82 ccw(c-694.48,3967.88) -694.48,3952.07 ; v1@-694.52,3986.81 cw(c-713.95,3967.38) -686.48,3967.38 ; v1@-691.69,3989.63 cw(c-704.29,3977.04) -686.48,3977.04 ; v1(-687.8,3993.52) -686.48,3992.19 -686.48,3960.07 -694.48,3952.07 ; -686.48,3973.8 cw(c-668.08,3973.8) v1@-681.09,3986.81 ; 1667.94,5276.75 ccw(c1684.68,5293.5) R133.1@1684.68,5269.81 ; 1669.12,5275.56 cw(c1654.06,5260.49) R133.1@1675.37,5260.49 ; R133.1@1674.76,5269.92 ccw(c1684.68,5279.84) R133.1@1684.68,5265.81 ; R133.1@1675.95,5268.73 cw(c1667.71,5260.49) R133.1@1679.37,5260.49 ; R133.1@1684.68,5260 1650,5294.68 1650,5525 1853.07,5728.07 J13.2@1853.07,5880 ; J13.2@1825.25,5852.18 cw(c1758.1,5785.03) 1853.07,5785.03 cw(c1948.04,5785.03) J13.2@1880.89,5852.18 ; J13.2@1828.08,5855.01 cw(c1767.75,5794.68) 1853.07,5794.68 cw(c1938.38,5794.69) J13.2@1878.06,5855.01 ; J13.2@1830.91,5857.84 cw(c1777.41,5804.34) 1853.07,5804.34 cw(c1928.73,5804.34) J13.2@1875.23,5857.84 ; J13.2@1833.74,5860.67 cw(c1787.07,5814) 1853.07,5814 ; J13.2@1836.57,5863.5 cw(c1796.73,5823.65) 1853.07,5823.65 cw(c1909.41,5823.66) J13.2@1869.57,5863.5 ; J13.2@1839.4,5866.33 cw(c1806.38,5833.31) 1853.07,5833.31 cw(c1899.76,5833.31) J13.2@1866.75,5866.33 ; 1853.07,5814 cw(c1919.07,5814) J13.2@1872.4,5860.67
  MidLayer1 w4: v4@1193.06,5031.94 ccw(c1176.31,5048.69) 1200,5048.69 ccw(c1223.69,5048.69) v4@1206.94,5031.94 ; v4@1195.89,5029.11 ccw(c1185.97,5039.03) 1200,5039.03 ccw(c1214.03,5039.03) v4@1204.11,5029.11 ; v4(1200,5025) 1200,5310 1239.84,5349.84 v4(1239.84,5420.16) ; v4@1232.9,5413.22 cw(c1216.16,5396.47) 1239.84,5396.47 cw(c1263.53,5396.47) v4@1246.78,5413.22 ; v4@1235.73,5416.05 cw(c1225.81,5406.13) 1239.84,5406.13 cw(c1253.87,5406.13) v4@1243.95,5416.05
  Bottom Layer w4: v1(-687.8,3993.52) -573.27,3993.52 -567.25,3987.5 -522.35,3987.5 -451,4058.85 -451,4375.52 -250.48,4576.04 205.04,4576.04 259,4630 284,4630 302,4648 353,4648 375,4670 375,4980 410.19,5015.19 1155.19,5015.19 1165,5025 v4(1200,5025) ; v1@-683.92,3989.63 cw(c-674.53,3980.24) -674.53,3993.52 cw(c-674.53,4006.8) v1@-683.92,3997.41 ; v1@-681.09,3986.81 cw(c-664.87,3970.59) -664.87,3993.52 cw(c-664.87,4016.46) v1@-681.09,4000.24 ; v4@1193.06,5018.06 ccw(c1176.31,5001.31) 1176.31,5025 ccw(c1176.31,5048.69) v4@1193.06,5031.94 ; v4@1195.89,5020.89 ccw(c1185.97,5010.97) 1185.97,5025 ccw(c1185.97,5039.03) v4@1195.89,5029.11 ; v4@1232.9,5427.1 ccw(c1216.16,5443.84) 1239.84,5443.84 ccw(c1263.53,5443.84) v4@1246.78,5427.1 ; v4@1235.73,5424.27 ccw(c1225.81,5434.19) 1239.84,5434.19 ccw(c1253.87,5434.19) v4@1243.95,5424.27 ; v4(1239.84,5420.16) 1239.84,5640 ; 1239.84,5574.69 1239.84,5640 ; J13.2@1813.74,5880.92 ccw(c1726.05,5882.97) 1788.07,5945 ccw(c1850.1,6007.02) J13.2@1852.15,5919.33 ; J13.2@1817.74,5880.83 ccw(c1738.96,5882.67) 1794.68,5938.39 ccw(c1850.4,5994.11) J13.2@1852.24,5915.33 ; J13.2@1821.74,5880.73 ccw(c1751.88,5882.37) 1801.29,5931.78 ccw(c1850.71,5981.19) J13.2@1852.34,5911.33 ; J13.2@1825.74,5880.64 ccw(c1764.79,5882.06) 1807.9,5925.17 ccw(c1851.01,5968.28) J13.2@1852.43,5907.33 ; J13.2@1829.74,5880.55 ccw(c1777.71,5881.76) 1814.51,5918.56 ccw(c1851.31,5955.36) J13.2@1852.53,5903.33 ; J13.2@1833.74,5880.45 ccw(c1790.63,5881.46) 1821.12,5911.95 ccw(c1851.61,5942.44) J13.2@1852.62,5899.33 ; J13.2@1853.07,5880 1788.07,5945 1360,5945 1239.84,5824.84 1239.84,5640
ADC#.ADC1: J13.3 J33.A8 R134.1 | length 5287.6
  Top Layer w4: J33.A8@-785.98,3991.44 -714.63,3991.44 -691.08,4015 -648.1,4015 v1(-608.14,3975.04) ; v1@-617.64,3975.04 ccw(c-640.58,3975.04) -624.36,3991.26 ccw(c-608.14,4007.48) v1@-608.14,3984.54 ; v1@-613.64,3975.04 ccw(c-626.92,3975.04) -617.53,3984.43 ccw(c-608.14,3993.82) v1@-608.14,3980.54 ; v1@1608.47,4790.09 ccw(c1592.26,4806.31) 1615.19,4806.31 ccw(c1638.13,4806.31) v1@1621.91,4790.09 ; v1@1611.3,4787.26 ccw(c1601.91,4796.65) 1615.19,4796.65 ccw(c1628.47,4796.65) v1@1619.08,4787.26 ; v1(1615.19,4783.37) 1615.19,5100.04 1706.86,5191.71 1706.86,5285 1684.68,5307.17 R134.1@1684.68,5415 1684.68,5514.76 J13.3@2049.92,5880 ; R134.1@1678.1,5407.92 cw(c1662.19,5392.01) 1684.68,5392.01 cw(c1707.18,5392.01) R134.1@1691.27,5407.92 ; R134.1@1678.1,5422.08 ccw(c1662.19,5437.99) 1684.68,5437.99 ccw(c1707.18,5437.99) R134.1@1691.27,5422.08 ; R134.1@1680.92,5410.75 cw(c1671.84,5401.67) 1684.68,5401.67 cw(c1697.53,5401.67) R134.1@1688.45,5410.75 ; R134.1@1680.92,5419.25 ccw(c1671.84,5428.33) 1684.68,5428.33 ccw(c1697.53,5428.33) R134.1@1688.45,5419.25 ; J13.3@2010.58,5880 cw(c1915.61,5880) 1982.77,5812.84 cw(c2049.92,5745.69) J13.3@2049.92,5840.66 ; J13.3@2014.58,5880 cw(c1929.27,5880) 1989.59,5819.67 cw(c2049.92,5759.35) J13.3@2049.92,5844.66 ; J13.3@2018.58,5880 cw(c1942.92,5880) 1996.42,5826.5 cw(c2049.92,5773) J13.3@2049.92,5848.66 ; J13.3@2022.58,5880 cw(c1956.58,5880) 2003.25,5833.33 cw(c2049.92,5786.66) J13.3@2049.92,5852.66 ; J13.3@2026.58,5880 cw(c1970.24,5880) 2010.08,5840.16 cw(c2049.92,5800.32) J13.3@2049.92,5856.66 ; J13.3@2030.58,5880 cw(c1983.9,5880) 2016.91,5846.99 cw(c2049.92,5813.97) J13.3@2049.92,5860.66
  MidLayer2 w4: v1(-608.14,3975.04) -593.14,3990.04 -593.14,4006.61 -575.75,4024 -557.96,4024 -318.14,4263.82 v1(-318.14,4391.71) ; v1@-324.86,4384.99 cw(c-341.08,4368.77) -318.14,4368.77 cw(c-295.21,4368.77) v1@-311.43,4384.99 ; v1@-322.03,4387.82 cw(c-331.42,4378.43) -318.14,4378.43 cw(c-304.86,4378.43) v1@-314.25,4387.82
  Bottom Layer w4: v1@-324.86,4398.43 ccw(c-341.08,4414.64) -318.14,4414.64 ccw(c-295.21,4414.64) v1@-311.43,4398.43 ; v1@-322.03,4395.6 ccw(c-331.42,4404.99) -318.14,4404.99 ccw(c-304.86,4404.99) v1@-314.25,4395.6 ; v1(-318.14,4391.71) -318.14,4474.43 -240.53,4552.04 300.08,4552.04 300.12,4552 468.46,4552 591.5,4675.04 1006.86,4675.04 1015.19,4683.37 1015.19,4741.71 1031.86,4758.37 1590.19,4758.37 v1(1615.19,4783.37) ; v1@1605.69,4783.37 cw(c1582.76,4783.37) 1598.97,4767.16 cw(c1615.19,4750.94) v1@1615.19,4773.87 ; v1@1609.69,4783.37 cw(c1596.41,4783.37) 1605.8,4773.99 cw(c1615.19,4764.6) v1@1615.19,4777.87
ADC#.ADC2: J13.4 J33.A12 R135.1 | length 6235.8
  Top Layer w4: J33.A12@-785.98,3755.22 -557.61,3755.22 -542.5,3770.33 -542.5,4082.5 -555,4095 v1(-600,4095) ; J33.A12@-711.58,3749.72 cw(c-698.3,3736.44) -698.3,3755.22 cw(c-698.3,3774) J33.A12@-711.58,3760.72 ; J33.A12@-708.76,3746.89 cw(c-688.65,3726.79) -688.65,3755.22 cw(c-688.65,3783.66) J33.A12@-708.76,3763.55 ; v1@-596.11,4091.11 cw(c-586.72,4081.72) -586.72,4095 cw(c-586.72,4108.28) v1@-596.11,4098.89 ; v1@-593.28,4088.28 cw(c-577.07,4072.06) -577.07,4095 cw(c-577.07,4117.93) v1@-593.28,4101.72 ; v4@2103.06,5468.06 cw(c2074.23,5439.23) 2115,5439.23 ; v4@2105.89,5470.89 cw(c2083.89,5448.89) 2115,5448.89 ; v4@2108.72,5473.72 cw(c2093.55,5458.55) 2115,5458.55 ; v4(2110,5475) 2115,5470 2115,5432.04 R135.1@2132.05,5415 ; 2115,5463.39 cw(c2121.61,5463.39) v4@2116.94,5468.06 ; 2115.3,5431.75 ccw(c2132.05,5448.5) R135.1@2132.05,5424.81 ; 2116.49,5430.56 cw(c2101.42,5415.49) R135.1@2122.73,5415.49 ; R135.1@2122.13,5424.92 ccw(c2132.05,5434.84) R135.1@2132.05,5420.81 ; R135.1@2123.32,5423.73 cw(c2115.08,5415.49) R135.1@2126.73,5415.49
  MidLayer1 w4: v4@2103.06,5481.94 ccw(c2086.31,5498.69) 2110,5498.69 ccw(c2133.69,5498.69) v4@2116.94,5481.94 ; v4@2105.89,5479.11 ccw(c2095.97,5489.03) 2110,5489.03 ccw(c2124.03,5489.03) v4@2114.11,5479.11 ; v4(2110,5475) 2110,5743.23 J13.4@2246.77,5880 ; J13.4@2207.43,5880 cw(c2112.46,5880) 2179.62,5812.84 cw(c2246.77,5745.69) J13.4@2246.77,5840.66 ; J13.4@2211.43,5880 cw(c2126.12,5880) 2186.44,5819.67 cw(c2246.77,5759.35) J13.4@2246.77,5844.66 ; J13.4@2215.43,5880 cw(c2139.77,5880) 2193.27,5826.5 cw(c2246.77,5773) J13.4@2246.77,5848.66 ; J13.4@2219.43,5880 cw(c2153.43,5880) 2200.1,5833.33 cw(c2246.77,5786.66) J13.4@2246.77,5852.66 ; J13.4@2223.43,5880 cw(c2167.09,5880) 2206.93,5840.16 cw(c2246.77,5800.32) J13.4@2246.77,5856.66 ; J13.4@2227.43,5880 cw(c2180.75,5880) 2213.76,5846.99 cw(c2246.77,5813.97) J13.4@2246.77,5860.66
  MidLayer2 w4: v1(-600,4095) -550,4145 -550,4175.2 -507.98,4217.22 -507.98,4576.77 -462.25,4622.5 -328.91,4622.5 -285.28,4578.87 -222.75,4578.87 -192.25,4609.37 83.31,4609.37 163.75,4689.82 193.94,4720 430,4720 469.5,4759.5 469.5,4950.5 460,4960 460,5298.69 463.31,5302 796.69,5302 836.69,5262 1033,5262 1103.29,5191.71 1361.71,5191.71 1391.02,5221.02 1391.02,5342.53 1490.19,5441.71 1798.52,5441.71 1815.19,5458.37 2031.86,5458.37 2035.23,5455 2092.05,5455 v4@2110,5472.95 ; 2093.07,5456.02 ccw(c2075.79,5473.31) v4@2100.2,5474.52 ; 2096.75,5459.7 cw(c2110,5446.45) v4@2110,5465.19 ; 2099.45,5462.4 ccw(c2087.94,5473.91) v4@2104.2,5474.71
ADC#.ADC3: J13.5 J33.A10 R136.1 | length 7885.5
  Top Layer w4: J33.A10@-785.98,3912.7 -719,3912.7 -705,3926.71 ; J33.A10@-714.25,3924.14 ccw(c-711.9,3933.61) -705,3926.71 ; J33.A10@-706.49,3917.85 cw(c-699.53,3921.23) -705,3926.71 ; v1@88.28,5893.28 ccw(c72.06,5877.06) 72.06,5900 ccw(c72.06,5922.93) v1@88.28,5906.72 ; v1@91.11,5896.11 ccw(c81.72,5886.72) 81.72,5900 ccw(c81.72,5913.28) v1@91.11,5903.89 ; v1(95,5900) -446.48,5900 -551.48,5795 -551.48,4700.04 -609.81,4641.71 -609.81,4618.63 -592.06,4600.87 -591.93,4600.87 -536,4544.94 -536,4196.69 -549,4183.69 -549,4124.5 -561,4112.5 -635.68,4112.5 -642.5,4105.68 -642.5,4067.69 -632.62,4057.81 -592.81,4057.81 -584.81,4049.81 -584.81,3943.37 -601.48,3926.71 -705,3926.71 ; v4(2105,5305) 2120,5305 2132.05,5292.95 R136.1@2132.05,5260 ; R136.1@2125.46,5267.08 ccw(c2109.55,5282.99) 2132.05,5282.99 ccw(c2154.54,5282.99) R136.1@2138.64,5267.08 ; R136.1@2128.29,5264.25 ccw(c2119.21,5273.33) 2132.05,5273.33 ccw(c2144.89,5273.33) R136.1@2135.81,5264.25 ; v4@2141.06,5457.56 ccw(c2124.31,5474.31) 2148,5474.31 ccw(c2171.69,5474.31) v4@2154.94,5457.56 ; v4@2143.89,5454.73 ccw(c2133.97,5464.65) 2148,5464.65 ccw(c2162.03,5464.65) v4@2152.11,5454.73 ; v4(2148,5450.62) 2148,5478.9 2122.69,5504.21 2122.69,5737.88 2214.81,5830 2393.62,5830 ; J13.5@2405.32,5871.03 cw(c2362.6,5861.03) 2393.62,5830 ; J13.5@2409.21,5871.94 cw(c2370.84,5862.96) 2398.71,5835.09 cw(c2426.58,5807.21) J13.5@2435.56,5845.59 ; J13.5@2413.11,5872.85 cw(c2379.08,5864.89) 2403.79,5840.17 cw(c2428.51,5815.45) J13.5@2436.48,5849.49 ; J13.5@2417,5873.77 cw(c2387.31,5866.81) 2408.88,5845.25 cw(c2430.44,5823.69) J13.5@2437.39,5853.38 ; J13.5@2420.9,5874.68 cw(c2395.55,5868.74) 2413.96,5850.34 cw(c2432.37,5831.93) J13.5@2438.3,5857.28 ; J13.5@2434.65,5841.7 ccw(c2424.65,5798.98) 2393.62,5830 ; J13.5@2443.62,5880 2393.62,5830
  MidLayer1 w4: v1@88.28,5893.28 cw(c72.06,5877.06) 95,5877.06 cw(c117.93,5877.06) v1@101.72,5893.28 ; v1@91.11,5896.11 cw(c81.72,5886.72) 95,5886.72 cw(c108.28,5886.72) v1@98.89,5896.11 ; v1(95,5900) 95,5830 120,5805 v4(205,5805) ; v4@198.06,5798.06 ccw(c181.31,5781.31) 181.31,5805 ccw(c181.31,5828.69) v4@198.06,5811.94 ; v4@200.89,5800.89 ccw(c190.97,5790.97) 190.97,5805 ccw(c190.97,5819.03) v4@200.89,5809.11 ; v4@2098.06,5311.94 ccw(c2081.31,5328.69) 2105,5328.69 ccw(c2128.69,5328.69) v4@2111.94,5311.94 ; v4@2100.89,5309.11 ccw(c2090.97,5319.03) 2105,5319.03 ccw(c2119.03,5319.03) v4@2109.11,5309.11 ; v4(2105,5305) 2105,5407.62 v4(2148,5450.62) ; v4@2138.19,5450.62 cw(c2114.5,5450.62) 2131.25,5433.87 cw(c2148,5417.13) v4@2148,5440.81 ; v4@2142.19,5450.62 cw(c2128.16,5450.62) 2138.08,5440.7 cw(c2148,5430.78) v4@2148,5444.81
  MidLayer2 w4: v4@205,5795.19 cw(c205,5771.5) 221.75,5788.25 cw(c238.5,5805) v4@214.81,5805 ; v4@205,5799.19 cw(c205,5785.16) 214.92,5795.08 cw(c224.84,5805) v4@210.81,5805 ; v4(205,5805) 230,5780 1240,5780 1337.73,5877.73 1395.32,5935.32 2258.4,5935.32 2313.72,5880 J13.5@2443.62,5880 ; J13.5@2415.81,5852.18 ccw(c2348.65,5785.03) 2348.65,5880 ccw(c2348.65,5974.97) J13.5@2415.81,5907.82 ; J13.5@2418.63,5855.01 ccw(c2358.31,5794.69) 2358.31,5880 ccw(c2358.31,5965.31) J13.5@2418.63,5904.99 ; J13.5@2421.46,5857.84 ccw(c2367.96,5804.34) 2367.96,5880 ccw(c2367.96,5955.66) J13.5@2421.46,5902.16 ; J13.5@2424.29,5860.67 ccw(c2377.62,5814) 2377.62,5880 ccw(c2377.62,5946) J13.5@2424.29,5899.33 ; J13.5@2427.12,5863.5 ccw(c2387.28,5823.66) 2387.28,5880 ccw(c2387.28,5936.34) J13.5@2427.12,5896.5 ; J13.5@2429.95,5866.33 ccw(c2396.93,5833.31) 2396.93,5880 ccw(c2396.93,5926.69) J13.5@2429.95,5893.67
ADC.CLK: U8.B13 U24.10 | length 7985.1
  Top Layer w4: U24.10@1824.29,5305.63 1862.45,5305.63 1881.86,5325.04 1881.86,5471.86 1899.36,5489.36 1899.36,5630 2056.67,5787.32 2085,5787.32 2107.32,5787.32 2115,5795 2115,5930 1945,6100 1945,6345 1856.86,6433.14 v1(1856.86,6521.04) ; v1@1850.14,6514.32 cw(c1833.92,6498.11) 1856.86,6498.11 cw(c1879.79,6498.11) v1@1863.57,6514.32 ; v1@1852.97,6517.15 cw(c1843.58,6507.76) 1856.86,6507.76 cw(c1870.14,6507.76) v1@1860.75,6517.15 ; U24.10@1854.58,5302.8 cw(c1861.41,5295.97) 1861.41,5305.63 cw(c1861.41,5315.29) U24.10@1854.58,5308.46 ; U8.B13@5362.97,4642.76 ccw(c5345.25,4642.76) 5357.78,4655.29 ; v1@5363.52,4750.04 5365.31,4751.83 v1@5365.31,4754.69 ; v1(5365,4755) v1@5365.31,4754.69 ; U8.B13@5370.31,4650.1 cw(c5370.31,4667.83) 5357.78,4655.29 ; 5357.78,4655.29 cw(c5364.96,4662.47) 5354.81,4662.47 5354.81,4710 5354.81,4720 5354.81,4744.18 v1@5365.31,4754.69
  MidLayer1 w4: v1@1847.36,6521.04 ccw(c1824.42,6521.04) 1840.64,6537.26 ccw(c1856.86,6553.48) v1@1856.86,6530.54 ; v1@1851.36,6521.04 ccw(c1838.08,6521.04) 1847.47,6530.43 ccw(c1856.86,6539.82) v1@1856.86,6526.54 ; v1(1856.86,6521.04) 1813,6564.9 1813,6726.69 1833.31,6747 4716.69,6747 4810,6653.69 4810,6261.71 4830,6241.71 5617.98,6241.71 5702,6157.69 5702,5564.63 5682.19,5544.82 5682.19,5447.39 5480,5245.2 5480,5142.9 5503.86,5119.04 5503.86,5005.37 5440.69,4942.21 5440.69,4939.48 5415.19,4913.98 5415.19,4883.37 5373.52,4841.71 5373.52,4800 5365,4791.48 v1(5365,4755) 5371.58,4755 v1@5373.52,4756.94 ; v1@5358.28,4761.72 ccw(c5342.06,4777.93) 5365,4777.93 ccw(c5387.93,4777.93) v1@5371.72,4761.72 ; v1@5361.11,4758.89 ccw(c5351.72,4768.28) 5365,4768.28 ccw(c5378.28,4768.28) v1@5368.89,4758.89
ADC.CS: U8.G3 U24.1 | length 3896.9
  Top Layer w4: 1981.86,5286.67 cw(c2004.66,5286.67) U24.1@1988.54,5302.8 ; 1981.86,5296.33 cw(c1995.01,5296.33) U24.1@1985.71,5305.63 1981.86,5301.78 1981.86,4950.04 v1(2015.19,4916.71) ; v1@2005.69,4916.71 ccw(c1982.76,4916.71) 1998.97,4932.93 ccw(c2015.19,4949.14) v1@2015.19,4926.21 ; v1@2009.69,4916.71 ccw(c1996.41,4916.71) 2005.8,4926.1 ccw(c2015.19,4935.49) v1@2015.19,4922.21 ; v1(4415.19,4516.71) 4431.86,4533.37 4607.94,4533.37 4633.27,4508.04 4633.54,4508.04 4651.04,4490.55 4707.61,4490.55 4712.94,4495.87 4736.28,4495.87 4766.28,4465.87 4780.63,4465.87 4784.52,4469.76 4794.76,4469.76 4812,4469.76 4851.26,4469.76 4855.26,4469.77 4860,4469.77 4870,4469.77 4936.73,4469.77 ; v1@4415.19,4522.21 ccw(c4415.19,4535.49) 4424.58,4526.1 ccw(c4433.97,4516.71) v1@4420.69,4516.71 ; v1@4415.19,4526.21 ccw(c4415.19,4549.14) 4431.41,4532.93 ccw(c4447.63,4516.71) v1@4424.69,4516.71 ; 4936.73,4469.77 cw(c4936.73,4431.09) 4964.08,4458.44 ; 4936.73,4469.77 cw(c4936.73,4431.09) 4964.08,4458.44 ; 4964.08,4458.44 ccw(c4976.61,4470.97) 4976.61,4453.25 cw(c4976.61,4470.97) 4964.08,4458.44 ; 4964.08,4458.44 cw(c4951.55,4445.91) 4969.27,4445.91 ccw(c4951.55,4445.91) 4964.08,4458.44
  MidLayer2 w4: v1(2015.19,4916.71) 3700.9,4916.71 4099.9,4517.71 4414.19,4517.71 v1(4415.19,4516.71) ; v1@2019.08,4912.82 cw(c2028.47,4903.43) 2028.47,4916.71 cw(c2028.47,4929.99) v1@2019.08,4920.6 ; v1@2021.91,4909.99 cw(c2038.13,4893.77) 2038.13,4916.71 cw(c2038.13,4939.64) v1@2021.91,4923.43 ; 4389.84,4517.71 cw(c4389.84,4491.36) v1@4408.47,4509.99 ; 4394.67,4517.71 ccw(c4394.67,4537.23) v1@4408.47,4523.43 ; 4399.5,4517.71 cw(c4399.5,4501.02) v1@4411.3,4512.82
ADC.DIN: U8.F2 U24.8 | length 4316.3
  Top Layer w4: U24.8@1794,5342.17 ccw(c1787.17,5335.34) 1787.17,5345 ccw(c1787.17,5354.66) U24.8@1794,5347.83 ; v1@1858.47,5184.99 ccw(c1842.26,5168.77) 1842.26,5191.71 ccw(c1842.26,5214.64) v1@1858.47,5198.43 ; v1@1861.3,5187.82 ccw(c1851.91,5178.43) 1851.91,5191.71 ccw(c1851.91,5204.99) v1@1861.3,5195.6 ; v1(1865.19,5191.71) 1808.29,5191.71 1775,5225 1775,5340 1780,5345 U24.8@1818.8,5345 ; v1@4619,4541.16 cw(c4607.46,4527.71) 4625.19,4527.71 ; v1@4621.61,4544.2 cw(c4614.93,4536.41) 4625.19,4536.41 cw(c4635.45,4536.41) v1@4628.77,4544.2 ; v1(4625.19,4548.37) 4625.19,4527.71 ; v1@4631.38,4541.16 ccw(c4642.92,4527.71) 4625.19,4527.71 ; 4856.86,4500.78 4855.26,4500.78 4860,4500.78 ; U24.8@1818.8,5345 1796.83,5345 U24.8@1818.8,5345 ; U24.8@1818.8,5345 U24.8@1824.29,5345 U24.8@1818.8,5345 ; 4625.19,4527.71 4653.52,4499.37 4654.35,4498.55 4704.3,4498.55 4710.13,4504.37 4771.72,4504.37 4775.31,4500.78 4860,4500.78 ; 4860,4500.78 4870,4500.78 4917.53,4500.78 ; 4917.53,4500.78 cw(c4917.53,4490.63) 4924.71,4497.81 ; 4917.53,4500.78 cw(c4917.53,4490.63) 4924.71,4497.81 ; 4924.71,4497.81 cw(c4912.17,4485.28) 4929.9,4485.28 ccw(c4912.17,4485.28) 4924.71,4497.81 ; 4924.71,4497.81 ccw(c4937.24,4510.34) 4937.24,4492.62 cw(c4937.24,4510.34) 4924.71,4497.81
  MidLayer2 w4: v1(1865.19,5191.71) 1931.86,5191.71 1998.52,5258.37 2115.19,5258.37 2131.38,5242.19 2420,5242.19 2448.52,5270.71 2448.52,5366.71 2448.52,5375.04 2465.19,5391.71 2631.86,5391.71 2923.52,5100.04 4213.86,5100.04 4326.09,4987.81 4337.38,4987.81 4581.86,4743.33 4581.86,4591.71 v1(4625.19,4548.37) ; v1@1869.08,5187.82 cw(c1878.47,5178.43) 1878.47,5191.71 cw(c1878.47,5204.99) v1@1869.08,5195.6 ; v1@1871.91,5184.99 cw(c1888.13,5168.77) 1888.13,5191.71 cw(c1888.13,5214.64) v1@1871.91,5198.43 ; v1@4615.69,4548.37 ccw(c4592.76,4548.37) 4608.97,4564.59 ccw(c4625.19,4580.81) v1@4625.19,4557.87 ; v1@4619.69,4548.37 ccw(c4606.41,4548.37) 4615.8,4557.76 ccw(c4625.19,4567.15) v1@4625.19,4553.87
